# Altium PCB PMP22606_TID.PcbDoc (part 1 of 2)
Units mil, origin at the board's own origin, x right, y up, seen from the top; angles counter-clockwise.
Board outline 6300 x 4500 mil, 2 copper layers (Top Layer, Bottom Layer), stack 62 mil thick; 94 components, 37 nets, 207 pads, 120 vias.
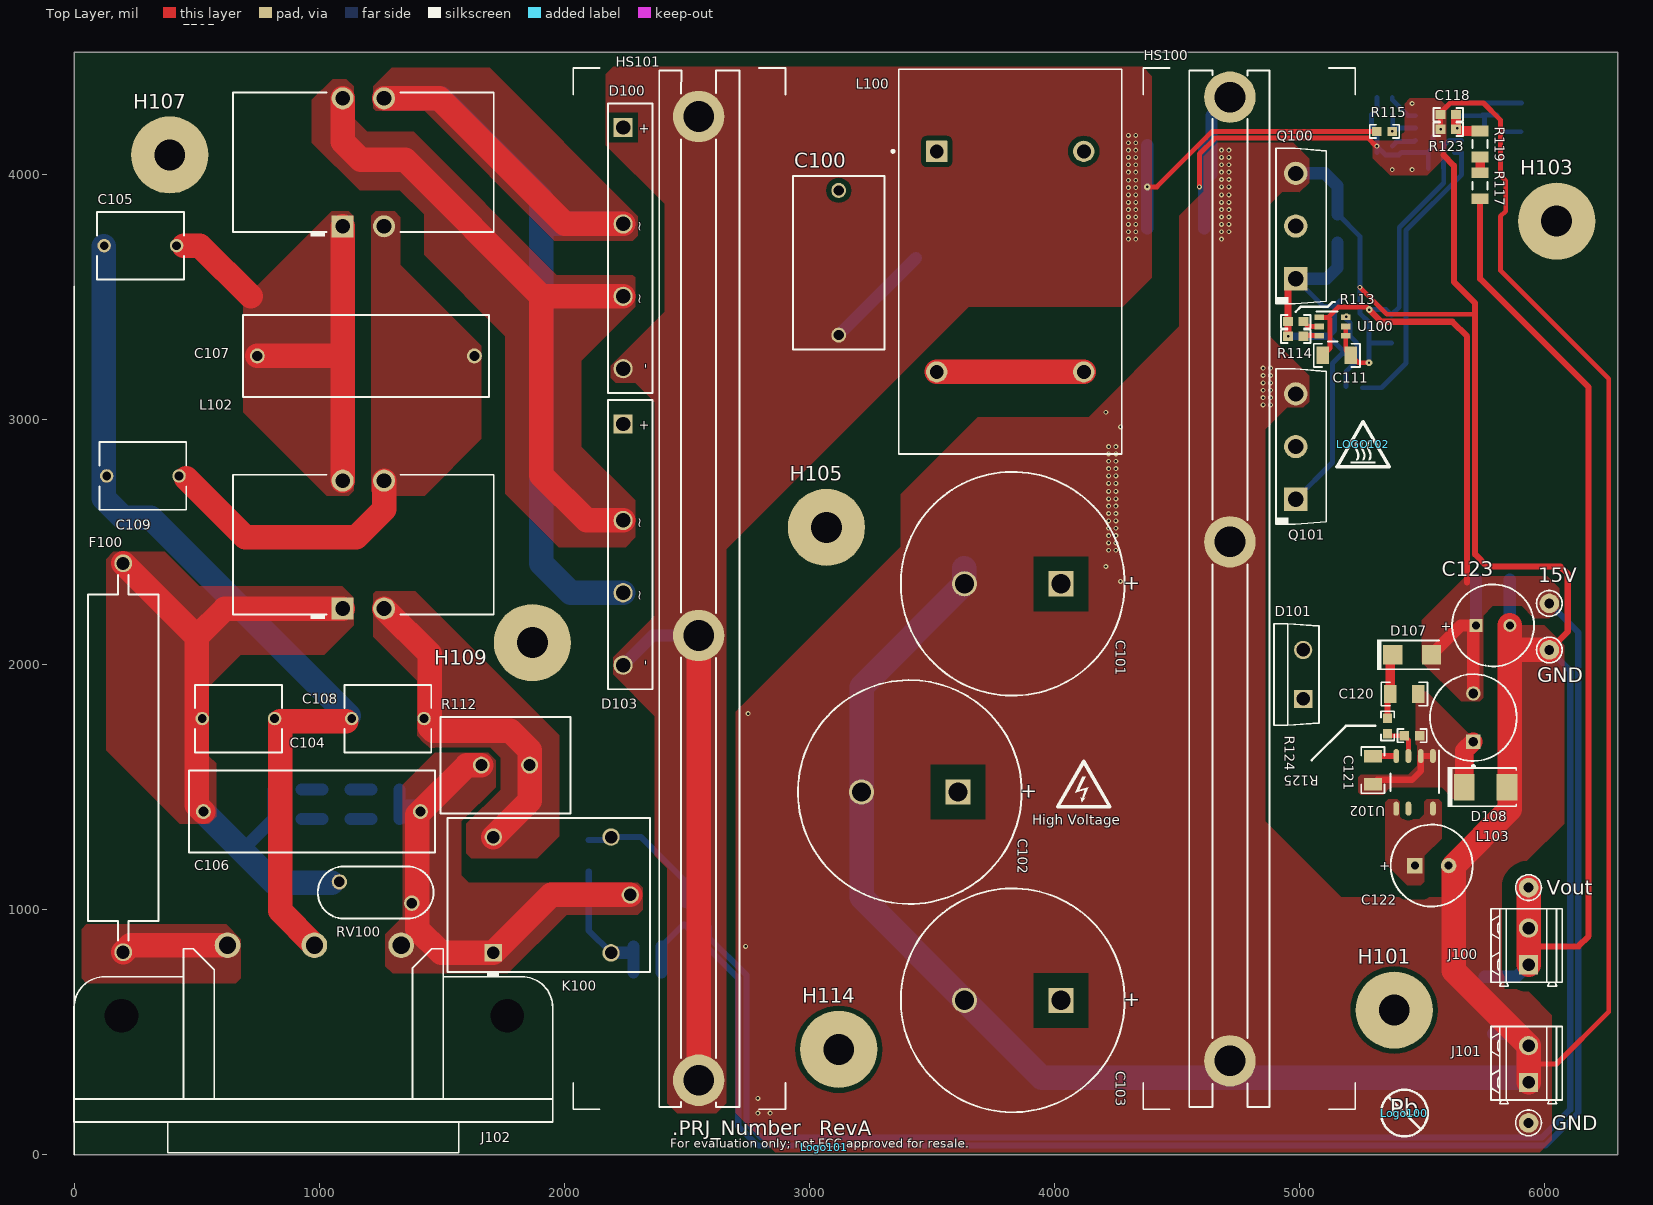
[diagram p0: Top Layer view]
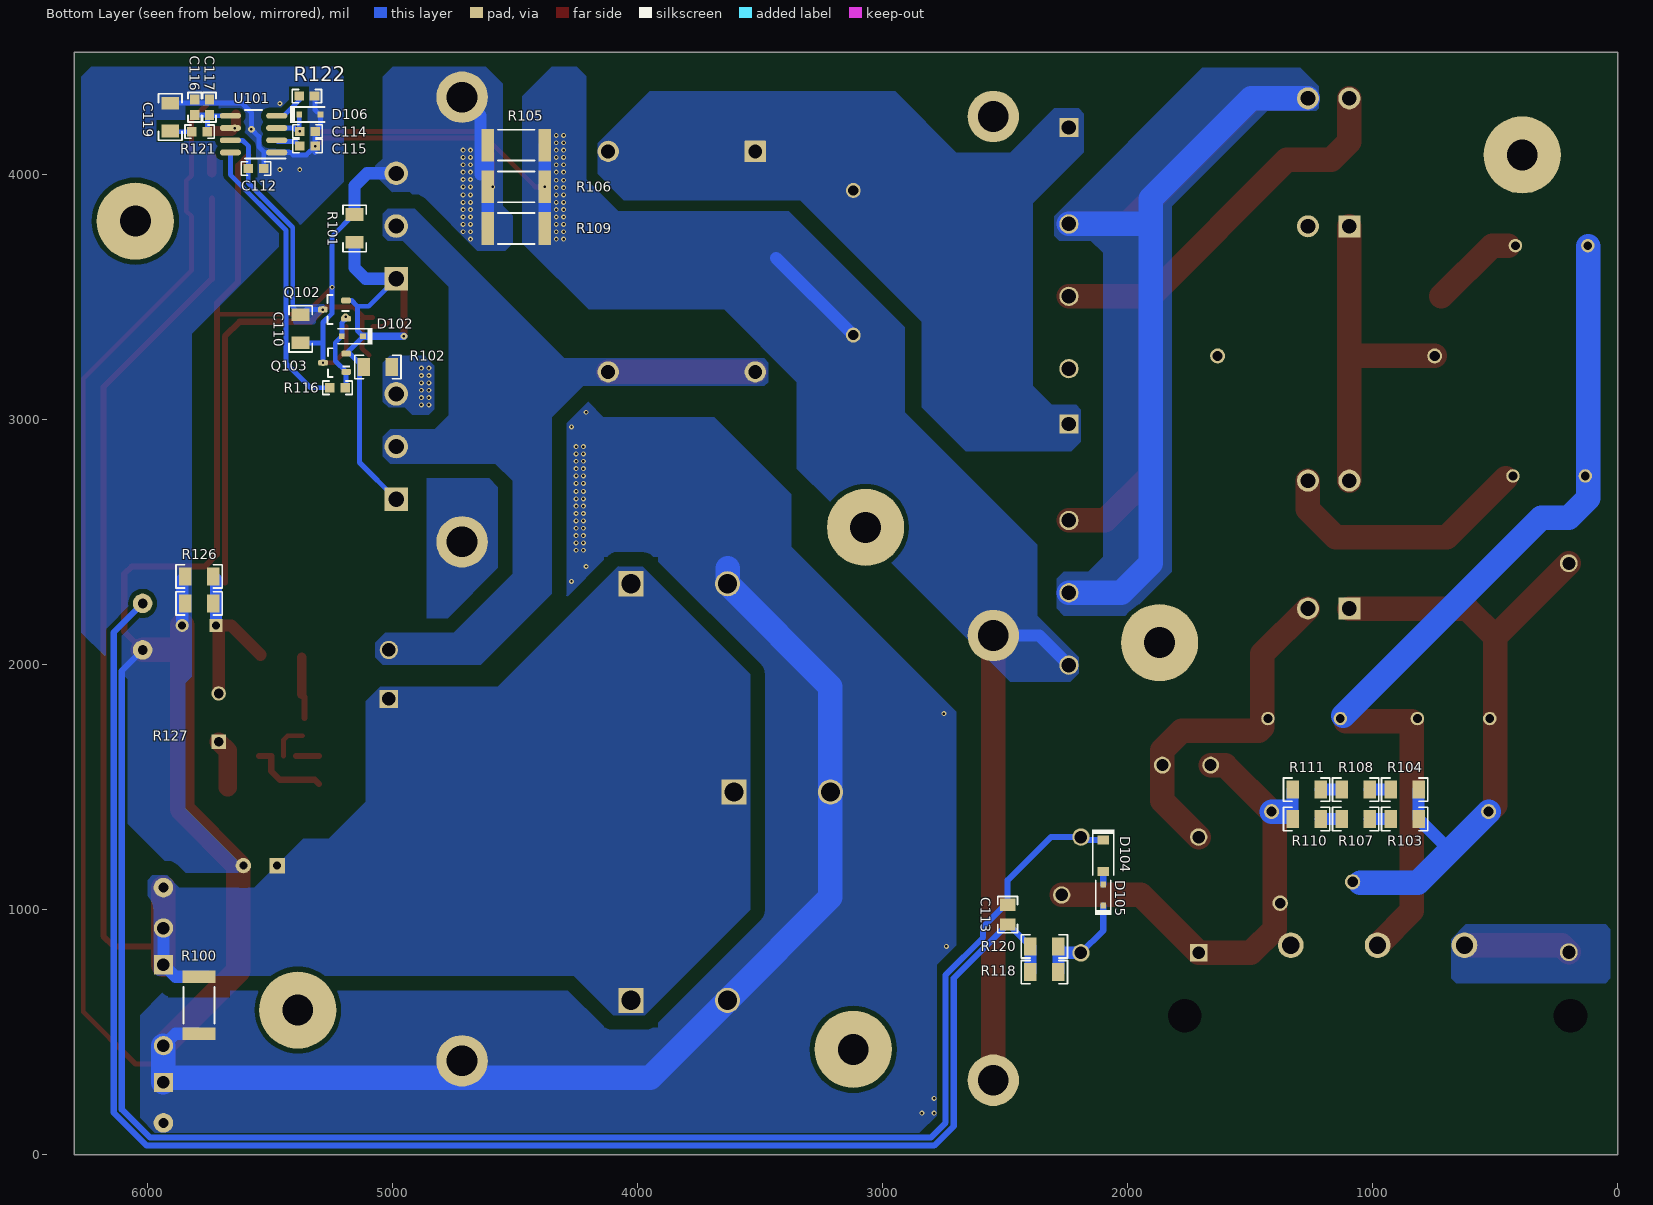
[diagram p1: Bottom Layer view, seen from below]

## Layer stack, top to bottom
Top Solder: solder mask 0.4, Solder Resist, Dk 3.5
Top Layer: signal copper 1.4
Dielectric1: core 59.2, FR-4, Dk 4.8
Bottom Layer: signal copper 1.4
Bottom Solder: solder mask 0.4, Solder Resist, Dk 3.5

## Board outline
0,0 6300,0 6300,4500 0,4500

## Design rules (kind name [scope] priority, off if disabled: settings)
AcuteAngle [All] p1: minimum=4.50000000000000E+0001 checktracksonly=FALSE
AssemblyTestPointUsage [All] p1: valid=2
Clearance Clearance_1 [InNetClass('HV') vs (InNet('GND') OR InNet('NetC103_2'))] p1: gap=60 ignorepadtopadclearanceinfootprint=FALSE except(0: Arc-Hole Track-Hole SMDPad-Hole THPad-Hole Via-Hole Fill-Hole Poly-Hole Region-Hole Text-Hole)
Clearance Clearance_Keepouts [((IsTrack Or IsArc) And Not InPoly) And IsFree and IsKeepOut vs ((IsTrack Or IsArc) And Not InPoly) And IsFree and IsKeepOut] p2: gap=0 ignorepadtopadclearanceinfootprint=FALSE
Clearance Clearance_BoardEdge_MountingHoles [OnCopper and InComponentClass('Mounting Holes') vs IsKeepOut] p3: gap=40 ignorepadtopadclearanceinfootprint=FALSE except(0: Arc-Hole Track-Hole SMDPad-Hole THPad-Hole Via-Hole Fill-Hole Poly-Hole Region-Hole Text-Hole)
Clearance Clearance_BoardEdge_Poly [OnCopper and InPoly vs IsKeepOut] p4: gap=25 ignorepadtopadclearanceinfootprint=FALSE except(0: Arc-Hole Track-Hole SMDPad-Hole THPad-Hole Via-Hole Fill-Hole Poly-Hole Region-Hole Text-Hole)
Clearance Clearance_BoardEdge [OnCopper and Not InComponentClass('Logo') and not InComponentClass('FiducialMark') and not InRegion(1000,500,4000,800) and Not IsKeepout vs IsKeepOut] p5: gap=75 ignorepadtopadclearanceinfootprint=FALSE except(0: Arc-Hole Track-Hole SMDPad-Hole THPad-Hole Via-Hole Fill-Hole Poly-Hole Region-Hole Text-Hole)
Clearance Clearance_Poly [InPolygon] p6: gap=20 ignorepadtopadclearanceinfootprint=FALSE except(0: Arc-Hole Track-Hole SMDPad-Hole THPad-Hole Via-Hole Fill-Hole Poly-Hole Region-Hole Text-Hole)
Clearance [All] p7: gap=7.87 ignorepadtopadclearanceinfootprint=FALSE except(0: Arc-Hole Track-Hole SMDPad-Hole THPad-Hole Via-Hole Fill-Hole Poly-Hole Region-Hole Text-Hole)
ComponentClearance ComponentClearance_MountingHoles_FiducialMarks [InComponentClass('Mounting Holes') vs InComponentClass('FiducialMark')] p1: gap=20 collisioncheckmode=3 verticalgap=10 showdistances=FALSE
ComponentClearance ComponentClearance_Shunt [InComponentClass('Header') vs InComponentClass('Shunt')] p2: gap=0 collisioncheckmode=3 verticalgap=0 showdistances=FALSE
ComponentClearance ComponentClearance_Logo [InComponentClass('Logo')] p3: gap=5 collisioncheckmode=3 verticalgap=10 showdistances=FALSE
ComponentClearance ComponentClearance_ScrewToNut [(HasFootprint('NY PMS 440 0025 PH')) vs (HasFootprint('Keystone_1902C'))] p4: gap=20 collisioncheckmode=3 verticalgap=100000 showdistances=FALSE
ComponentClearance ComponentClearance_MountingHoles [InComponentClass('Mounting Holes')] p5: gap=20 collisioncheckmode=3 verticalgap=10 showdistances=FALSE
ComponentClearance ComponentClearance_SmallPassives [HasFootprint('0201*') or HasFootprint('0402*') or HasFootprint('0508') or HasFootprint('0603*') or HasFootprint('0612') or HasFootprint('0805*') or HasFootprint('0815*') or HasFootprint('0830*') or HasFootprint('1206*') or HasFootprint('1210*') or HasFootprint('1808*') or HasFootprint('1812*') or HasFootprint('1825*') or HasFootprint('2010*') or HasFootprint('2220*') or HasFootprint('2225*') or HasFootprint('2512*') or HasFootprint('2728*') or HasFootprint('3518*') vs HasFootprint('0201*') or HasFootprint('0402*') or HasFootprint('0508') or HasFootprint('0603*') or HasFootprint('0612') or HasFootprint('0805*') or HasFootprint('0815*') or HasFootprint('0830*') or HasFootprint('1206*') or HasFootprint('1210*') or HasFootprint('1808*') or HasFootprint('1812*') or HasFootprint('1825*') or HasFootprint('2010*') or HasFootprint('2220*') or HasFootprint('2225*') or HasFootprint('2512*') or HasFootprint('2728*') or HasFootprint('3518*')] p6: gap=20 collisioncheckmode=3 verticalgap=20 showdistances=FALSE
ComponentClearance ComponentClearance_THtoSMT [IsThruComponent vs IsSMTComponent] p7: gap=10 collisioncheckmode=3 verticalgap=10 showdistances=FALSE
ComponentClearance ComponentClearance_THtoTH [IsThruComponent vs IsThruComponent] p8: gap=10 collisioncheckmode=3 verticalgap=10 showdistances=FALSE
ComponentClearance [All] p9: gap=10 collisioncheckmode=3 verticalgap=10 showdistances=FALSE
DiffPairsRouting [All] p1: maxlimit=100 minlimit=10 mostfreqgap=10 toplayer_minwidth=15 toplayer_maxwidth=15 toplayer_prefwidth=15 bottomlayer_minwidth=15 bottomlayer_maxwidth=15 bottomlayer_prefwidth=15 maxuncoupledlength=1000
FabricationTestPointUsage TestPointUsage [All] p1: valid=2 allowmultiple=FALSE
FabricationTestpoint Testpoint [All] p1: side=3 testpointundercomponent=TRUE minsize=40 maxsize=100 preferedsize=60 minholesize=0 maxholesize=40 preferedholesize=32 testpointgrid=1 allowsidetop=TRUE allowsidebottom=TRUE usegrid=TRUE gridtolerance=0.01
FanoutControl Fanout_LCC [IsLCC] p1: bgadir=Out bgaviamode=Centered fanoutstyle=Auto fanoutdirection=Alternating viagrid=1 // Fanout_LCC (Default Rule)
FanoutControl Fanout_BGA [IsBGA] p2: bgadir=Out bgaviamode=Centered fanoutstyle=Auto fanoutdirection=Alternating viagrid=1 // Fanout_BGA (Default Rule)
FanoutControl Fanout_Default [All] p4: bgadir=Out bgaviamode=Centered fanoutstyle=Auto fanoutdirection=Alternating viagrid=1 // Fanout_Default (Default Rule)
FanoutControl Fanout_Small [(CompPinCount < 5)] p5: bgadir=Out bgaviamode=Centered fanoutstyle=Auto fanoutdirection=OutThenIn viagrid=1 // Fanout_Small (Default Rule)
Height [All] p1: minheight=0 maxheight=3000 prefheight=500
HoleSize [All] p1: absolutevalues=TRUE maxlimit=251 minlimit=7 maxpercent=80.000 minpercent=20.000
MinimumAnnularRing MinimumAnnularRing_ThermalPadVias [IsVia and InAnyComponent] p1: minimumring=5.91
MinimumAnnularRing [All] p2: minimumring=5
MinimumSolderMaskSliver MinimumSolderMaskSliver_Logo [InComponentClass('Logo') vs InComponentClass('Logo')] p1: minsoldermaskwidth=0.7
MinimumSolderMaskSliver [All] p2: minsoldermaskwidth=2
PlaneConnect [All] p1: planeconnectstyle=Relief reliefexpansion=10 reliefentries=4 reliefconductorwidth=10 reliefairgap=10
PolygonConnect PolygonConnect_8 [All vs IsNamedPolygon('C104_1') Or  IsNamedPolygon('GND') Or  IsNamedPolygon('B+') Or  IsNamedPolygon('B+') Or  IsNamedPolygon('C107_2') Or  IsNamedPolygon('D100_2') Or  IsNamedPolygon('15V') Or  IsNamedPolygon('C106_2') Or  IsNamedPolygon('C120_2') Or  IsNamedPolygon('C100_2') Or  IsNamedPolygon('GND') Or  IsNamedPolygon('D101_2') Or  IsNamedPolygon('C105_1') Or  IsNamedPolygon('F100_1') Or  IsNamedPolygon('D100_3') Or  IsNamedPolygon('C108_2') Or  IsNamedPolygon('C100_1') Or  IsNamedPolygon('F100_1') Or  IsNamedPolygon('D100_2') Or  IsNamedPolygon('C100_2')] p1: connectstyle=Direct reliefconductorwidth=10 reliefentries=4 polygonreliefangle="90 Angle" airgapwidth=10
PolygonConnect PolygonConnect_7 [All vs IsNamedPolygon('F100_1') Or  IsNamedPolygon('C103_1') Or  IsNamedPolygon('C106_1') Or  IsNamedPolygon('D100_2') Or  IsNamedPolygon('C106_1') Or  IsNamedPolygon('C105_1') Or  IsNamedPolygon('C109_2') Or  IsNamedPolygon('B+') Or  IsNamedPolygon('C107_2') Or  IsNamedPolygon('C108_2') Or  IsNamedPolygon('F100_1') Or  IsNamedPolygon('C103_2') Or  IsNamedPolygon('C107_2') Or  IsNamedPolygon('D100_3') Or  IsNamedPolygon('D101_2')] p2: connectstyle=Direct reliefconductorwidth=10 reliefentries=4 polygonreliefangle="90 Angle" airgapwidth=10
PolygonConnect PolygonConnect_6 [All vs IsNamedPolygon('GND2') Or  IsNamedPolygon('SGND') Or  IsNamedPolygon('GND1') Or  IsNamedPolygon('C901_1') Or  IsNamedPolygon('SGND') Or  IsNamedPolygon('GND2') Or  IsNamedPolygon('GND1')] p3: connectstyle=Direct reliefconductorwidth=10 reliefentries=4 polygonreliefangle="90 Angle" airgapwidth=10
PolygonConnect PolygonConnect_5 [All vs IsNamedPolygon('GND1') Or  IsNamedPolygon('GND1')] p4: connectstyle=Direct reliefconductorwidth=10 reliefentries=4 polygonreliefangle="90 Angle" airgapwidth=10
PolygonConnect PolygonConnect_4 [All vs IsNamedPolygon('C21_1') Or  IsNamedPolygon('C5_1') Or  IsNamedPolygon('C12_2') Or  IsNamedPolygon('C2_2') Or  IsNamedPolygon('C13_1') Or  IsNamedPolygon('C28_1') Or  IsNamedPolygon('C6_1') Or  IsNamedPolygon('GND') Or  IsNamedPolygon('GND2') Or  IsNamedPolygon('C14_1') Or  IsNamedPolygon('C13_1') Or  IsNamedPolygon('Q1_3') Or  IsNamedPolygon('C14_1') Or  IsNamedPolygon('C5_1') Or  IsNamedPolygon('GND2') Or  IsNamedPolygon('C28_1') Or  IsNamedPolygon('D5_2') Or  IsNamedPolygon('D6_2') Or  IsNamedPolygon('D2_1') Or  IsNamedPolygon('C12_2') Or  IsNamedPolygon('D2_1') Or  IsNamedPolygon('C4_1') Or  IsNamedPolygon('C4_1') Or  IsNamedPolygon('C2_2') Or  IsNamedPolygon('GND') Or  IsNamedPolygon('C33_1') Or  IsNamedPolygon('C9_1')] p5: connectstyle=Direct reliefconductorwidth=10 reliefentries=4 polygonreliefangle="90 Angle" airgapwidth=10
PolygonConnect PolygonConnect_3 [All vs IsNamedPolygon('C28_1') Or  IsNamedPolygon('C12_2') Or  IsNamedPolygon('C28_1') Or  IsNamedPolygon('C9_1') Or  IsNamedPolygon('D5_2') Or  IsNamedPolygon('C12_2') Or  IsNamedPolygon('C2_2') Or  IsNamedPolygon('C14_1') Or  IsNamedPolygon('C4_1') Or  IsNamedPolygon('C14_1') Or  IsNamedPolygon('D6_2') Or  IsNamedPolygon('GND2') Or  IsNamedPolygon('Q1_3') Or  IsNamedPolygon('C5_1') Or  IsNamedPolygon('D2_1') Or  IsNamedPolygon('C4_1') Or  IsNamedPolygon('C13_1') Or  IsNamedPolygon('C5_1') Or  IsNamedPolygon('C13_1') Or  IsNamedPolygon('C33_1') Or  IsNamedPolygon('D2_1') Or  IsNamedPolygon('GND') Or  IsNamedPolygon('GND') Or  IsNamedPolygon('GND2') Or  IsNamedPolygon('C2_2') Or  IsNamedPolygon('C6_1') Or  IsNamedPolygon('C21_1')] p6: connectstyle=Direct reliefconductorwidth=10 reliefentries=4 polygonreliefangle="90 Angle" airgapwidth=10
PolygonConnect PolygonConnect_2 [All vs IsNamedPolygon('C21_1') Or  IsNamedPolygon('C4_1') Or  IsNamedPolygon('D5_2') Or  IsNamedPolygon('C5_1') Or  IsNamedPolygon('C14_1') Or  IsNamedPolygon('C13_1') Or  IsNamedPolygon('C4_1') Or  IsNamedPolygon('C33_1') Or  IsNamedPolygon('C12_2') Or  IsNamedPolygon('D2_1') Or  IsNamedPolygon('C2_2') Or  IsNamedPolygon('C28_1') Or  IsNamedPolygon('C12_2') Or  IsNamedPolygon('D2_1') Or  IsNamedPolygon('C5_1') Or  IsNamedPolygon('Q1_3') Or  IsNamedPolygon('GND') Or  IsNamedPolygon('D6_2') Or  IsNamedPolygon('C6_1') Or  IsNamedPolygon('C2_2') Or  IsNamedPolygon('C14_1') Or  IsNamedPolygon('C28_1') Or  IsNamedPolygon('C13_1') Or  IsNamedPolygon('C9_1') Or  IsNamedPolygon('GND')] p7: connectstyle=Direct reliefconductorwidth=10 reliefentries=4 polygonreliefangle="90 Angle" airgapwidth=10
PolygonConnect PolygonConnect_1 [All vs IsNamedPolygon('C28_1') Or  IsNamedPolygon('D5_2') Or  IsNamedPolygon('C5_1') Or  IsNamedPolygon('C5_1') Or  IsNamedPolygon('D2_1') Or  IsNamedPolygon('C21_1') Or  IsNamedPolygon('C9_1') Or  IsNamedPolygon('C4_1') Or  IsNamedPolygon('C14_1') Or  IsNamedPolygon('C28_1') Or  IsNamedPolygon('C6_1') Or  IsNamedPolygon('C12_2') Or  IsNamedPolygon('C33_1') Or  IsNamedPolygon('C4_1') Or  IsNamedPolygon('C13_1') Or  IsNamedPolygon('C12_2') Or  IsNamedPolygon('D6_2') Or  IsNamedPolygon('C2_2') Or  IsNamedPolygon('C14_1') Or  IsNamedPolygon('D2_1') Or  IsNamedPolygon('C2_2') Or  IsNamedPolygon('C13_1')] p8: connectstyle=Direct reliefconductorwidth=10 reliefentries=4 polygonreliefangle="90 Angle" airgapwidth=10
PolygonConnect [All] p9: connectstyle=Relief reliefconductorwidth=10 reliefentries=4 polygonreliefangle="90 Angle" airgapwidth=10
RoutingVias ThermalPadVias [IsVia and InAnyComponent] p1: holewidth=7.87 width=19.68 viastyle="Through Hole" minholewidth=7.87 minwidth=19.68 maxholewidth=12.99 maxwidth=23.62
RoutingVias [All] p2: holewidth=10 width=34 viastyle="Through Hole" minholewidth=7.87 minwidth=20 maxholewidth=40 maxwidth=65
SilkToBoardRegionClearance [Not ((IsComment or IsDesignator) And (Hide <> 'False')) and not InRegion(1000,500,4000,800)] p1:
SilkToSilkClearance SilkToSilkClearance_Pb-FreeLogo [(HasFootprint('Pb-Free_Overlay_Medium') OR HasFootprint('Pb-Free_Overlay_Small')) vs (HasFootprint('Pb-Free_Overlay_Medium') OR HasFootprint('Pb-Free_Overlay_Small'))] p1: silktosilkclearance=0
SilkToSilkClearance [All] p2: silktosilkclearance=1
SilkToSolderMaskClearance "Silk to Solder Mask Opening" [All] p1: minsilkscreentomaskgap=1 clearancetoexposedcopper=FALSE
SolderMaskExpansion [All] p1: expansion=1.97
Width [All] p1: maxlimit=100 minlimit=6 preferedwidth=10 checkconnectedcopper=TRUE
14 further rules are at their usual default settings.

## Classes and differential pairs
net class HV: B+ NetC100_1 NetC104_1 NetC105_1 NetC106_2 NetC108_2 NetD101_2 NetF100_1
component class "Mounting Holes": H101 H103 H105 H107 H109 H114

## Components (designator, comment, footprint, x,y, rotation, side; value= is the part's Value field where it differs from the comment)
15V "5000" Keystone5000 6020,2250 r0 top
C100 "450MPK105J" MPK_1800x950 3120,3640 r270 top value=1uF
C101 "450HXG180MEFCSN22X45" SMQ_2200X2500 3830,2330 r180 top value=180uF
C102 "450HXG180MEFCSN22X45" SMQ_2200X2500 3410,1480 r180 top value=180uF
C103 "450HXG180MEFCSN22X45" SMQ_2200X2500 3830,630 r180 top value=180uF
C104 "DE6E3KJ222MN3A" E_900x700x900 670,1780 r0 top value=2200pF
C105 "DE6E3KJ222MN3A" E_900x700x900 270,3710 r180 top value=2200pF
C106 "ECQ-U2A474ML" CAPRR2250W80L2550T850H1750 970,1400 r0 top value=0.47uF
C107 "ECQ-U2A474ML" CAPRR2250W80L2550T850H1750 1190,3260 r0 top value=0.47uF
C108 "DE6E3KJ222MN3A" E_900x700x900 1280,1780 r0 top value=2200pF
C109 "DE6E3KJ222MN3A" E_900x700x900 280,2770 r0 top value=2200pF
C110 "C3216X7R1H105K160AB" 1206 5375.2,3370 r270 bottom value=1uF
C111 "C3216X7R1H105K160AB" 1206 5152.88,3262.49 r0 top value=1uF
C112 "C0603C474K8RACTU" 0603 5557.52,4024.88 r180 bottom value=0.47uF
C113 "0805YD105KAT2A" 0805_HV 2490,980 r270 bottom value=1uF
C114 "06031C471JAT2A" 0603 5347.52,4176.34 r180 bottom value=470pF
C115 "C0603C102J5RACTU" 0603 5347.52,4116.34 r180 bottom value=1000pF
C116 "C0603C105K4PACTU" 0603 5807.52,4274.88 r90 bottom value=1uF
C117 "C0603C474K8RACTU" 0603 5747.52,4274.88 r90 bottom value=0.47uF
C118 "CL10C102JB8NNNC" 0603 5607.52,4244.88 r180 top value=1000pF
C119 "GRM31MR61A106KE19L" 1206 5907.52,4234.88 r90 bottom value=10uF
C120 "12065C104JAT2A" 1206 5428.5,1880 r0 top value=0.1uF
C121 "12065C223KAT2A" 1206 5300,1569.56 r270 top value=0.022uF
C122 "ECA-2WHG010" NHG_800x1150 5540,1180 r0 top value=1uF
C123 "EKMG250ELL221MHB5D" Chemi-Con_800x1150 5790,2160 r0 top value=220uF
D100 "DFB2560" 5S 2240,3700 r270 top value=600V
D101 "CVFD20065A" TO-220-2 5015.2,1960 r90 top value=650V
D102 "BAT54HT1G" sod-323 5163.9,3340.16 r0 bottom value=30V
D103 "DFB2560" 5S 2240,2490 r270 top value=600V
D104 "MMSZ4699T1G" SOD-123 2100,1220 r270 bottom value=12V
D105 "BAS316,115" sod-323 2100,1060 r90 bottom value=100V
D106 "MMDL914-TP" SOD-323 5337.52,4244.88 r180 bottom value=100V
D107 "ES1J-TP" SMA 5460,2040 r0 top value=600V
D108 "MURS160-13-F" SMB 5760,1500.05 r0 top value=600V
F100 "0325020.MXP" FUSE_0325 200,1620 r90 top
GND "5001" Keystone5001 5935.2,130 r90 top
GND "5001" Keystone5001 6020,2060 r90 top
H101 "NY PMS 440 0025 PH" "NY PMS 440 0025 PH" 5386.93,590.32 r0 top
H103 "NY PMS 440 0025 PH" "NY PMS 440 0025 PH" 6050,3810 r0 top
H105 "NY PMS 440 0025 PH" "NY PMS 440 0025 PH" 3070,2560 r0 top
H107 "NY PMS 440 0025 PH" "NY PMS 440 0025 PH" 390,4080 r0 top
H109 "NY PMS 440 0025 PH" "NY PMS 440 0025 PH" 1870,2090 r0 top
H114 "NY PMS 440 0025 PH" "NY PMS 440 0025 PH" 3120,430 r0 top
"High Voltage" "DANGER HIGH VOLTAGE" IEC_HighVoltage_Small 4120,1507.56 r0 top (schematic designator "High Voltage100")
HS100 "782653B04250G" HEATSINK_782653B04250G 4795.2,2310 r270 top
HS101 "782653B04250G" HEATSINK_782653B04250G 2470,2310 r90 top
J100 "691214310002" Wurth_691214310002 5935.2,850 r90 top
J101 "691214310002" Wurth_691214310002 5935.2,370 r90 top
J102 "703W-00/54" CONN_QUALTEK-703W-0054 980,460 r180 top
K100 "G5LE-1-E-36-DC12" RELAY_875 1990,1060 r90 top
L100 "RLTI-1328" FP-RLTI-1328_PTH_INDUCTOR-MFG 3820,3644.77 r0 top
L101 "750318527" 7840-21-0021 1180,4050 r90 top value=1.68mH
L102 "750318527" 7840-21-0021 1180,2490 r90 top value=1.68mH
L103 "744741222" WE-TI_8055 5710,1784 r90 top value=2.2mH
Logo100 "Pb-Free Symbol" Pb-Free_Overlay_Medium 5428.5,170 r0 top
Logo101 "FCC disclaimer" FCC_disclaimer 3060,30 r0 top
LOGO102 "CAUTION HOT SURFACE" IEC_HotSurface_Small 5260,2900 r0 top
Q100 "IPW65R095C7" TO-247 4985.2,3790 r90 top value=650V
Q101 "IPW65R095C7" TO-247 4985.2,2890 r90 top value=650V
Q102 "FMMT620TA" SOT-23 5237.32,3449.06 r0 bottom value=80V
Q103 "FMMT718TA" SOT-23 5236.85,3232.17 r0 bottom value="20 V"
R100 "CRCW2512330KJNEG" 2512 5790,610 r90 bottom value=330k
R101 "CRCW120620K0JNEA" 1206 5155.2,3780 r270 bottom value=20k
R102 "CRCW120620K0JNEA" 1206 5060,3214.85 r0 bottom value=20k
R103 "CRCW1206432KFKEA" 1206 870,1370 r180 bottom value=432k
R104 "CRCW1206432KFKEA" 1206 870,1490 r180 bottom value=432k
R105 "1-2176057-4" 2512 4495.2,4120 r0 bottom value=0.036
R106 "1-2176057-4" 2512 4495.2,3950 r0 bottom value=0.036
R107 "CRCW1206432KFKEA" 1206 1070,1370 r180 bottom value=432k
R108 "CRCW1206432KFKEA" 1206 1070,1490 r180 bottom value=432k
R109 "1-2176057-4" 2512 4495.2,3780 r0 bottom value=0.036
R110 "CRCW1206432KFKEA" 1206 1270,1370 r180 bottom value=432k
R111 "CRCW1206432KFKEA" 1206 1270,1490 r180 bottom value=432k
R112 "TWW10J10RE" TWW10 1760,1590 r180 top value=10
R113 "CRCW060310R0JNEAHP" 0603 4985.2,3400 r0 top value=10
R114 "CRCW06030000Z0EA" 0603 4985.2,3340 r180 top value=0
R115 "CRCW0603221RFKEA" 0603 5347.52,4176.34 r180 top value=221
R116 "CRCW060310R0JNEAHP" 0603 5225.2,3130 r0 bottom value=10
R117 "CRCW1206499KFKEA" 1206L 5737.52,3954.88 r270 top value=499k
R118 "CRCW1206150RJNEA" 1206 2340,745.04 r0 bottom value=150
R119 "CRCW1206499KFKEA" 1206L 5737.52,4124.88 r270 top value=499k
R120 "CRCW1206150RJNEA" 1206 2340,850 r0 bottom value=150
R121 "CRCW06035K90FKEA" 0603 5787.52,4174.88 r180 bottom value=5.90k
R122 "CRCW060316K2FKEA" 0603 5350,4320 r0 bottom value=16.2k
R123 "CRCW060313K3FKEA" 0603 5607.52,4184.88 r0 top value=13.3k
R124 "CRCW0603137KFKEA" 0603 5360,1750 r90 top value=137k
R125 "CRCW060310K0FKEA" 0603 5460,1710 r180 top value=10.0k
R126 "CRCW120612K0JNEA" 1206 5789.69,2360 r180 bottom value=12k
R127 "CRCW120612K0JNEA" 1206 5789.69,2250 r180 bottom value=12k
RV100 "S10K275E2" VAR_S10K275E2 1230,1070 r180 top
U100 "UCC27511DBVR" DBV0006A_N 5135.2,3380 r0 top
U101 "UCC28180D" D0008A_N 5567.52,4164.88 r0 bottom
U102 "UCC28880DR" D0007A_N 5470,1519.74 r270 top
Vout "5000" Keystone5000 5935.2,1090 r90 top

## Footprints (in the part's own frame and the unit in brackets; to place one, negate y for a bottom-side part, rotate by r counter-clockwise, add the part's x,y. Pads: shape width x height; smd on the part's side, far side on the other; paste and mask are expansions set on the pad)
5S [mm] "TH, 4-Leads, Body 4.6x30mm"
  rect 2x2 hole 1.5: 1(-12.5,0)
  round 2 hole 1.5: 2(-2.5,0) 3(5,0) 4(12.5,0)
  silkscreen extent -15,-1.55 15,3.05, body extent -15,-1.55 15,3.05, height 24
0603 [mm] "0603 from SM-752 data"
  rect 1x0.95 smd: 1(-0.8,0) 2(0.8,0)
  silkscreen extent -1.52,-0.69 1.52,0.69, body extent -0.87,-0.47 0.87,0.47, height 1
0805_HV [mil] "0805 with 30mil clearance between pads"
  rect 50x63 smd: 1(-40,0) 2(40,0)
  silkscreen extent -74,-40 74,40, body extent -43,-29 43,29, height 43
1206 [mm] "1206 from SM-752 data"
  rect 1.3x1.85 smd: 1(-1.45,0) 2(1.45,0)
  silkscreen extent -2.4,-1.21 2.4,1.21, body extent -1.7,-0.9 1.7,0.9, height 1.35
1206L [mm] "1206 from SM-752 data"
  rect 1.1x1.75 smd: 1(-1.35,0) 2(1.35,0)
  silkscreen extent -0.4,-0.77 0.4,0.77, body extent -1.7,-0.9 1.7,0.9, height 1.35
2512 [mm] "Chip Resistor, Body 6.3x3.2mm, IPC Medium Density"
  rect 1.3x3.4 smd: 1(-2.95,0) 2(2.95,0)
  silkscreen extent -1.9,-1.6 1.9,1.6, body extent -3.22,-1.67 3.22,1.67, height 0.71
7840-21-0021 [mil] "TH, 4-Leads, Dia 1064mil"
  rect 90x90 hole 60: 1(-261,84.5)
  round 90 hole 60: 2(-261,-84.5) 3(261,-84.5) 4(261,84.5)
  silkscreen extent -303,-532 285,532, body extent -281,-532 281,532, height 1064
CAPRR2250W80L2550T850H1750 [mm] "PANASONIC"
  round 1.55 hole 1.05: 1(-11.25,0) 2(11.25,0)
  silkscreen extent -12.75,-4.25 12.75,4.25, body extent -12.75,-4.25 12.75,4.25, height 17.5
Chemi-Con_800x1150 [mm] "TH, 2-Leads, Dia 8mm"
  rect 1.35x1.35 hole 0.85: 1(-1.75,0)
  round 1.35 hole 0.85: 2(1.75,0)
  silkscreen extent -4.25,-4.25 4.25,4.25, body extent -4.22,-4.24 4.24,4.24, height 13.01
CONN_QUALTEK-703W-0054 [mil] "AC Receptacle"
  round 105 hole 70: 1(354.33,-395) 2(-354.33,-395) 3(0,-395)
  round 39.37 hole 137.8 unplated: MH1(-787.4,-107.36) MH2(787.4,-107.36)
  silkscreen extent -972,-380 981,452, body extent -972,-477 981,452, height 1130
D0007A_N [mm] "SOIC, 7-Leads, Body 4.9x3.9mm, Pitch 1.27mm, IPC Medium Density"
  oval 1.45x0.6 smd: 1(-2.725,1.905) 2(-2.725,0.635) 3(-2.725,-0.635) 4(-2.725,-1.905) 5(2.725,-1.905) 6(2.725,-0.635) 8(2.725,1.905)
  silkscreen extent -3.32,-2.5 1.1,2.52, body extent -3.01,-2.45 3.01,2.45, height 1.75
D0008A_N [mm] "SOIC, 8-Leads, Body 4.9x3.9mm, Pitch 1.27mm, IPC Medium Density"
  oval 2.2x0.6 smd: 1(-2.4,1.905) 2(-2.4,0.635) 3(-2.4,-0.635) 4(-2.4,-1.905) 5(2.4,-1.905) 6(2.4,-0.635) 7(2.4,0.635) 8(2.4,1.905)
  silkscreen extent -3.3,-2.5 0.9,2.5, body extent -3,-2.45 3,2.45, height 1.63
DBV0006A_N [mm] "SOT23, 6-Leads, Body 2.9x1.6mm, Pitch 0.95mm, Lead Span 2.8mm, IPC Medium Density"
  rrect17% 1x0.6 smd: 1(-1.375,0.95) 2(-1.375,0) 3(-1.375,-0.95) 4(1.375,-0.95) 5(1.375,0) 6(1.375,0.95)
  silkscreen extent -1.68,-1.55 0.5,1.55, body extent -1.42,-1.46 1.42,1.46, height 1.12
E_900x700x900 [mm] "TH, 2- Leads, Body 9x7mm, Pin Spacing 7.5mm"
  round 1.4 hole 0.9: 1(-3.75,0) 2(3.75,0)
  silkscreen extent -4.5,-3.5 4.5,3.5, body extent -4.49,-3.5 4.49,3.5, height 11.96
FCC_disclaimer [mil]
FP-RLTI-1328_PTH_INDUCTOR-MFG [mm]
  rrect5% 2.2x2.2 hole 1.45 paste-1000 mask+0: 1(-7.62,11.43)
  round 2.2 hole 1.45 paste-1000 mask+0: 2(7.62,11.43) 3(7.62,-11.43) 4(-7.62,-11.43)
  silkscreen extent -12.28,-19.94 11.56,19.94, body extent -11.66,-20.04 11.66,20.04, height 0.25
FUSE_0325 [mm] "TH, 2-Leads, Dia 6.985mm, Pin Spacing 40.32mm"
  round 1.85 hole 1.35: 1(-20.16,0) 2(20.16,0)
  silkscreen extent -18.95,-3.64 18.95,3.64, body extent -20.7,-3.64 20.7,3.64, height 7.26
HEATSINK_782653B04250G [mil] "Aavid"
  round 210 hole 125: 1(-2006.1,-78.66) 2(-191.14,-78.66) 3(1926.97,-78.66)
  silkscreen extent -2125,-433 2125,433, body extent -2125,-430 2120,420, height 1122
IEC_HighVoltage_Small [mil]
  silkscreen extent -107,-88 107,97
IEC_HotSurface_Small [mil]
  silkscreen extent -107,-93 107,92
Keystone5000 [mil] "For Keystone 500x miniature loop terminals"
  round 80 hole 40: 1(0,0)
  silkscreen extent -52,-52 52,52, body extent -49,-49 49,49, height 182
Keystone5001 [mil] "For Keystone 500x miniature loop terminals"
  round 80 hole 40: 1(0,0)
  silkscreen extent -52,-52 52,52, body extent -49,-49 49,49, height 182
MPK_1800x950 [mm] "TH, 2-Leads, Body 18x9.5mm, Lead Spacing 15mm"
  round 1.55 hole 1.05: 1(-7.5,0) 2(7.5,0)
  silkscreen extent -9,-4.75 9,4.75, body extent -9,-4.75 9,4.75, height 14
NHG_800x1150 [mm] "Panasonic"
  rect 1.6x1.6 hole 0.838: 1(-1.75,0)
  round 1.6 hole 0.838: 2(1.75,0)
  silkscreen extent -4.25,-4.25 4.25,4.25, body extent -4.25,-4.25 4.26,4.25, height 12.51
"NY PMS 440 0025 PH" [mm] "4-40 nylon screw and mounting hole"
  round 8 hole 3.2: 1(0,0)
  body extent -3.3,-3.3 3.3,3.3, height 2.69
Pb-Free_Overlay_Medium [mil]
  silkscreen extent -95,-95 95,95
RELAY_875 [mm] "TH, 5-Leads, Body 21x16mm"
  rect 1.8x1.8 hole 1.3: 1(-6,7.1)
  round 1.8 hole 1.3: 2(6,7.1) 3(0,-7.1) 4(-6,-5.1) 5(6,-5.1)
  silkscreen extent -8.5,-9.15 8,11.85, body extent -8,-9.15 8,11.85, height 20.6
SMA [mm] "Molded Diode, 2-Leads, Body 4.3x2.6mm, IPC Medium Density, based on OnSemi component dimensions and land pattern"
  rect 2x2 smd: 1(-2,0) 2(2,0)
  silkscreen extent -3.66,-1.57 2.79,1.57, body extent -2.6,-1.3 2.6,1.3, height 2.42
SMB [mil] "Molded Diode, 2-Leads, Body 5.4x3.6mm, IPC Medium Density, based on OnSemi component dimensions"
  rect 85x107.99 smd: 1(-87.01,0) 2(87.01,0)
  silkscreen extent -155,-82 125,82, body extent -106,-71 106,71, height 91
SMQ_2200X2500 [mm] "United Chemi-Con Inc"
  rect 2.6x2.6 hole 2: 1(-5,0)
  round 2.6 hole 2: 2(5,0)
  silkscreen extent -11.6,-11.6 11.6,11.6, body extent -11.41,-11.48 11.47,11.48, height 27.01
SOD-123 [mm] "On Semi recommended land pattern"
  rect 0.915x1.22 smd: 1(-1.637,0) 2(1.637,0)
  silkscreen extent -2.74,-1.17 2.03,1.17, body extent -1.93,-0.9 1.93,0.9, height 1.35
sod-323 [mm] "NXP recommended land pattern"
  rect 0.6x0.6 smd paste-0.05: 1(-1.1,0) 2(1.1,0)
  silkscreen extent -2.06,-0.86 1.53,0.86, body extent -1.3,-0.67 1.3,0.68, height 1.1
SOD-323 [mm] "NXP recommended land pattern"
  rect 0.6x0.6 smd paste-0.05: 1(-1.1,0) 2(1.1,0)
  silkscreen extent -2.06,-0.86 1.53,0.86, body extent -1.3,-0.67 1.3,0.68, height 1.1
SOT-23 [mm] "SOT23, 3-Leads, Body 2.9x1.3mm, Pitch 0.95mm, Lead Span 2.5mm, IPC Medium Density"
  rrect50% 1x0.6 smd: 1(-1.2,0.95) 2(-1.2,-0.95) 3(1.2,0)
  silkscreen extent -1.58,-1.5 0.7,1.5, body extent -1.16,-1.45 1.21,1.45, height 1
TO-220-2 [mm] "CREE"
  rect 1.9x1.9 hole 1.4: 1(-2.54,0)
  round 1.9 hole 1.4: 2(2.54,0)
  silkscreen extent -5.25,-1.64 5.26,3.01, body extent -5.21,-1.57 5.21,3.12, height 19.47
TO-247 [mil] "Standard TO-247"
  rect 95x95 hole 62: 1(-215,0)
  round 95 / inner round 74.8 / far side round 96 hole 62: 2(0,0) 3(215,0)
  silkscreen extent -318,-124 318,81, body extent -318,-124 318,81, height 1007
TWW10 [mm] "TH, 2-Leads, Body 13.5x10mm, Pin Spacing 5mm"
  round 1.75 hole 1.25: 1(-2.5,0) 2(2.5,0)
  silkscreen extent -6.75,-5 6.75,5, body extent -6.7,-5 6.81,5, height 50
VAR_S10K275E2 [mm] "EPCOS"
  round 1.6 hole 1.1: 1(-3.75,1.1) 2(3.75,-1.1)
  silkscreen extent -6,-2.7 6,2.7, body extent -5.98,-2.7 5.98,2.7, height 14.99
WE-TI_8055 [mm] "Wurth"
  rect 1.5x1.5 hole 1: 1(-2.5,0)
  round 1.5 hole 1: 2(2.5,0)
  silkscreen extent -5.21,-4.5 4.5,4.5, body extent -5.89,-5.88 5.81,5.83, height 5.51
Wurth_691214310002 [mm] "WE"
  rect 2x2 hole 1.3: 1(-1.905,0)
  round 2 hole 1.3: 2(1.905,0)
  silkscreen extent -4.12,-3.5 3.9,3.9, body extent -4.12,-3.5 3.9,3.9, height 8.52

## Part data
15V Vout: "Test Point, Miniature, Red, TH", Color=Red, Manufacturer=Keystone, Supplier Part Number 1=36-5000-ND
C100: "CAP, Film, 1 £gF, 450 V,+/- 5%, TH", Cap_Case=18x9.5mm, Manufacturer=Rubycon, Supplier Part Number 1=1189-1822-ND, Tolerance_%=5, Value2=450V, ValueDisplayed=1£gF
C101 C102 C103: library part ESMQ451VSN101MP25S, "CAP ALUM 180UF 450V 20% SNAP", Cap_Case=22x25, Manufacturer=Rubycon, Supplier Part Number 1=1189-1973-ND, Tolerance_%=20, Value1=Unknown, Value2=450V, ValueDisplayed=180£gF
C104 C105 C108 C109: "CAP, CERM, 2200 pF, 300 V, +/- 20%, E, TH, 2- Leads, Body 9x7mm, Pin Spacing 7.5mm", Cap_Case=9x7x9mm, Manufacturer=MuRata, Supplier Part Number 1=DE6E3KJ222MN3A-ND, TempCo=E, Tolerance_%=20, Value1=Unknown, Value2=300V, ValueDisplayed=2200pF
C106 C107: "CAP, Film, 0.47 £gF, 275 V, +/- 20%, TH", Cap_Case="Radial 25x8.5x18.5", Manufacturer=Panasonic, Supplier Part Number 1=P10734-ND, Tolerance_%=20, Value1=Unknown, Value2=275V, ValueDisplayed=0.47£gF
C110 C111: "CAP, CERM, 1 £gF, 50 V, +/- 10%, X7R, 1206", Cap_Case=1206, Manufacturer=TDK, Supplier Part Number 1=445-1423-1-ND, TempCo=X7R, Tolerance_%=10, Value1=Unknown, Value2=50V, ValueDisplayed=1£gF
C112 C117: "CAP, CERM, 0.47 £gF, 10 V, +/- 10%, X7R, 0603", Cap_Case=0603, Manufacturer=Kemet, Supplier Part Number 1=399-4923-1-ND, TempCo=X7R, Tolerance_%=10, Value1=Unknown, Value2=10V, ValueDisplayed=0.47£gF
C113: "CAP, CERM, 1uF, 16V, +/-10%, X5R, 0805", Cap_Case=0805, Manufacturer=AVX, Supplier Part Number 1=478-1411-1-ND, TempCo=X5R, Tolerance_%=10, Value1="0.012 ohm", Value2=16V, ValueDisplayed=1£gF
C114: "CAP, CERM, 470 pF, 100 V, +/- 5%, X7R, 0603", Cap_Case=0603, Manufacturer=AVX, Supplier Part Number 1=478-3709-1-ND, TempCo=X7R, Tolerance_%=5, Value1="0.397 ohm", Value2=100V, ValueDisplayed=470pF
C115: "CAP, CERM, 1000 pF, 50 V, +/- 5%, X7R, 0603", Cap_Case=0603, Manufacturer=Kemet, Supplier Part Number 1=399-1083-1-ND, TempCo=X7R, Tolerance_%=5, Value1=Unknown, Value2=50V, ValueDisplayed=1000pF
C116: "CAP, CERM, 1 £gF, 16 V, +/- 10%, X5R, 0603", Cap_Case=0603, Manufacturer=Kemet, Supplier Part Number 1=399-5090-1-ND, TempCo=X5R, Tolerance_%=10, Value1=Unknown, Value2=16V, ValueDisplayed=1£gF
C118: "CAP, CERM, 1000 pF, 50 V, +/- 5%, X7R, 0603", Cap_Case=0603, Manufacturer="Samsung Electro-Mechanics", Supplier Part Number 1=1276-1091-1-ND, TempCo=X7R, Tolerance_%=5, Value1=Unknown, Value2=50V, ValueDisplayed=1000pF
C119: "CAP, CERM, 10 £gF, 10 V, +/- 10%, X5R, 1206", Cap_Case=1206, Manufacturer=MuRata, Supplier Part Number 1=GRM31MR61A106KE19-ND, TempCo=X5R, Tolerance_%=10, Value1=Unknown, Value2=10V, ValueDisplayed=10£gF
C120: "CAP, CERM, 0.1uF, 50V, +/-5%, X7R, 1206", Cap_Case=1206, Manufacturer=AVX, Supplier Part Number 1=478-3797-1-ND, TempCo=X7R, Tolerance_%=5, Value1="0.037 ohm", Value2=50V, ValueDisplayed=0.1£gF
C121: "CAP, CERM, 0.022uF, 50V, +/-10%, X7R, 1206", Cap_Case=1206, Manufacturer=AVX, Supplier Part Number 1=478-1546-1-ND, TempCo=X7R, Tolerance_%=10, Value1="0.079 ohm", Value2=50V, ValueDisplayed=0.022µF
C122: "CAP, AL, 1 £gF, 450 V, +/- 20%, TH", Cap_Case=8x11.5mm, Manufacturer=Panasonic, Supplier Part Number 1=P5872-ND, Tolerance_%=20, Value2=450V, ValueDisplayed=1£gF
C123: "CAP, AL, 220 £gF, 25 V, +/- 20%, TH", Cap_Case=8x11.5mm, Manufacturer=Chemi-Con, Supplier Part Number 1=565-1308-ND, Tolerance_%=20, Value2=25V, ValueDisplayed=220£gF
D100 D103: library part D25XB60-7000, "Bridge Rectifiers 600V 25A Glass Pass. Bridge Rectifier", Manufacturer="On Semi", Value1=3.5A, Value2=1.05V
D101: library part C3D08060A, "DIODE SCHKY SIC 650V 20A TO-220", Manufacturer=Cree, Supplier Part Number 1=CVFD20065A-ND, Value1=20A, Value2=1.8V
D102: "Diode, Schottky, 30 V, 0.2 A, SOD-323", Manufacturer="ON Semiconductor", Supplier Part Number 1=BAT54HT1OSCT-ND, Value1=0.2A, Value2=0.35V
D104: "Diode, Zener, 12 V, 500 mW, SOD-123", Manufacturer="ON Semiconductor", Power_W=0.5, Supplier Part Number 1=MMSZ4699T1GOSCT-ND, Value1=0.5W
D105: "Diode, Ultrafast, 100 V, 0.25 A, SOD-323", Manufacturer="NXP Semiconductor", Supplier Part Number 1=568-5003-1-ND, Value1=0.25A, Value2=1.4V
D106: library part CMP-0029045-2, "Diode, Switching, 100 V, 0.2 A, SOD-323", Manufacturer="Micro Commercial Components", Value1=0.2A, Value2=1V
D107: library part ES1D-13-F, "DIODE FAST REC 600V 1A DO214AC", Manufacturer="Diodes Inc.", Supplier Part Number 1=ES1J-TPCT-ND, Value1=1A
D108: "Diode, Ultrafast, 600V, 1A, SMB", Manufacturer="Diodes Inc.", Supplier Part Number 1=MURS160-FDICT-ND, Value1=1A, Value2=1.25V
F100: "Fuse, 20 A, 60 V, TH", Irating_A=20A, Manufacturer=Littelfuse, Supplier Part Number 1=F3336-ND
GND GND: "Test Point, Miniature, Black, TH", Color=Black, Manufacturer=Keystone, Supplier Part Number 1=36-5001-ND
H101 H103 H105 H107 H109 H114: "Machine Screw, Round, #4-40 x 1/4, Nylon, Philips panhead", DigiKeyPartNumber=H542-ND, Manufacturer="B&F Fastener Supply"
"High Voltage": library part IEC_HighVoltage, "IEC 61010-1 High Voltage Warning"
HS100 HS101: "HEATSINK VERT MAX CLIP, BLACK, 4.25 INCHES", Manufacturer=Aavid, Supplier Part Number 1=782653B04250G-ND
J100 J101: "Terminal Block, 2x1, 3.81mm, 24-16 AWG, 10A, 300VAC, TH", Manufacturer="Wurth Elektronik eiSos"
J102: "AC Receptacle, 10A 250VAC", Manufacturer="Qualtek Electronics Corporation", Supplier Part Number 1=Q220-ND
K100: library part 875B-1CC-F-S-12VDC, "Relay, SPDT ( 1 Form C), 16A, 12 VDC, TH", Coil Current="30 mA", Coil Power="360 mW", Coil Resistance="400 ohms", Coil Voltage="12 VDC", Contact Rating=16A, Manufacturer=Omron, Turn Off Voltage (Min)="0.6 VDC", Turn On Voltage (Max)="9 VDC"
L100: library part CMP-0088184-1, "INDUCTOR WITH KOOL MU MAX CORE", Manufacturer="Renco Electronics"
L101 L102: library part 7840-21-0021, "Coupled inductor, 1.68 mH,  A,  ohm, TH", Manufacturer=Wurth, ValueDisplayed=1.68mH
L103: library part 744741101, "FIXED IND 2.2MH 210MA 11 OHM TH", Manufacturer="Wurth Elektronik", ValueDisplayed=2.2mH
Logo100: library part CMP-0074839-1
Logo101: library part CMP-0074847-1, "FCC_disclaimer"
LOGO102: library part IEC_HotSurface, "IEC 61010-1 Hot Surface Warning"
Q100 Q101: library part IPW60R045CP, "MOSFET N-CH 650V 24A TO247", Alternate Manufacturer=None, Manufacturer="Infineon Technologies", Supplier Part Number 1=IPW65R095C7XKSA1-ND, Value1="? ohm"
Q102: library part "FMMT497, Zetex", "TRANS NPN 80V 1.5A SOT23-3", Manufacturer=Diodes, Supplier Part Number 1=FMMT620CT-ND, Value1="0.5 A"
Q103: library part "FMMT718TA, Diodes Inc.", "Transistor, PNP, 20 V, 1.5 A, SOT-23", Manufacturer="Diodes Inc.", Supplier Part Number 1=FMMT718CT-ND, Value1="1.5 A", Value2=6
R100: "RES, 330 k, 5%, 1 W, 2512", Manufacturer=Vishay-Dale, Power_W=1, Supplier Part Number 1=541-330KXCT-ND, TempCo="200 ppm/C", Tolerance_%=5, Value1=5%, Value2=1W, Value_Code=330k
R101 R102: "RES, 20 k, 5%, 0.25 W, 1206", Manufacturer=Vishay-Dale, Power_W=0.25, Supplier Part Number 1=541-20KECT-ND, TempCo="200 ppm/C", Tolerance_%=5, Value1=5%, Value2=0.25W, Value_Code=20k0, ValueDisplayed=20k
R103 R104 R107 R108 R110 R111: "RES, 432 k, 1%, 0.25 W, 1206", Manufacturer=Vishay-Dale, Power_W=0.25, Supplier Part Number 1=541-432KFCT-ND, TempCo="100 ppm/C", Tolerance_%=1, Value1=1%, Value2=0.25W, Value_Code=432k
R105 R106 R109: library part WSL2512R0320FEA18, "RES SMD 0.036 OHM 1% 2W 2512", Manufacturer="TE Connectivity", Power_W=2, Supplier Part Number 1=A109683CT-ND, TempCo="75 ppm/C", Tolerance_%=1, Value1=1%, Value2=2W, Value_Code=R036, ValueDisplayed=0.036
R112: "RES, 10, 5%, 10 W, TH", Manufacturer=Ohmite, Power_W=10, TempCo="400 ppm/C", Tolerance_%=5, Value1=5%, Value2=10W, Value_Code=10R0
R113 R116: "RES, 10, 5%, 0.25 W, 0603", Manufacturer=Vishay-Dale, Power_W=0.25, Supplier Part Number 1=541-10SACT-ND, TempCo="200 ppm/C", Tolerance_%=5, Value1=5%, Value2=0.25W, Value_Code=10R0, ValueDisplayed=10
R114: "RES, 0, 5%, 0.1 W, 0603", Manufacturer=Vishay-Dale, Power_W=0.1, Supplier Part Number 1=541-0.0GCT-ND, TempCo="200 ppm/C", Tolerance_%=5, Value1=5%, Value2=0.1W, Value_Code=0000, ValueDisplayed=0
R115: "RES, 221, 1%, 0.1 W, 0603", Manufacturer=Vishay-Dale, Power_W=0.1, Supplier Part Number 1=541-221HCT-ND, TempCo="100 ppm/C", Tolerance_%=1, Value1=1%, Value2=0.1W, Value_Code=221R, ValueDisplayed=221
R117 R119: "RES, 499k ohm, 1%, 0.25W, 1206", Manufacturer=Vishay-Dale, Power_W=0.25, Supplier Part Number 1=541-499KFCT-ND, TempCo="100 ppm/C", Tolerance_%=1, Value1=1%, Value2=0.25W, Value_Code=499k
R118 R120: "RES, 150, 5%, 0.25 W, 1206", Manufacturer=Vishay-Dale, Power_W=0.25, Supplier Part Number 1=541-150ECT-ND, TempCo="200 ppm/C", Tolerance_%=5, Value1=5%, Value2=0.25W, Value_Code=150R, ValueDisplayed=150
R121: "RES, 5.90 k, 1%, 0.1 W, 0603", Manufacturer=Vishay-Dale, Power_W=0.1, Supplier Part Number 1=541-5.90KHCT-ND, TempCo="100 ppm/C", Tolerance_%=1, Value1=1%, Value2=0.1W, Value_Code=5k90, ValueDisplayed=5.90k
R122: "RES, 16.2 k, 1%, 0.1 W, 0603", Manufacturer=Vishay-Dale, Power_W=0.1, Supplier Part Number 1=541-16.2KHCT-ND, TempCo="100 ppm/C", Tolerance_%=1, Value1=1%, Value2=0.1W, Value_Code=16k2, ValueDisplayed=16.2k
R123: "RES, 13.3 k, 1%, 0.1 W, 0603", Manufacturer=Vishay-Dale, Power_W=0.1, Supplier Part Number 1=541-13.3KHCT-ND, TempCo="100 ppm/C", Tolerance_%=1, Value1=1%, Value2=0.1W, Value_Code=13k3, ValueDisplayed=13.3k
R124: "RES, 137 k, 1%, 0.1 W, 0603", Manufacturer=Vishay-Dale, Power_W=0.1, Supplier Part Number 1=541-137KHCT-ND, TempCo="100 ppm/C", Tolerance_%=1, Value1=1%, Value2=0.1W, Value_Code=137k
R125: "RES, 10.0k ohm, 1%, 0.1W, 0603", Manufacturer=Vishay-Dale, Power_W=0.1, Supplier Part Number 1=541-10.0KHCT-ND, TempCo="100 ppm/C", Tolerance_%=1, Value1=1%, Value2=0.1W, Value_Code=10k0
R126 R127: "RES, 12k ohm, 5%, 0.25W, 1206", Manufacturer=Vishay-Dale, Power_W=0.25, Supplier Part Number 1=541-12KECT-ND, TempCo="200 ppm/C", Tolerance_%=5, Value1=5%, Value2=0.25W, Value_Code=12k0
RV100: "Varistor 275V RMS 10MM Radial, TH", Manufacturer="EPCOS Inc", Supplier Part Number 1=495-1433-ND
U100: "Single-Channel High-Speed Low-Side Gate Driver (with 4-A Peak Source and 8-A Peak Sink), DBV0006A", Alternate Manufacturer="Texas Instruments", Alternate PartNumber=UCC27511DBVT
U101: "8-PIN CONTINUOUS CONDUCTION MODE (CCM) PFC CONTROLLER, D0008A", Alternate Manufacturer="Texas Instruments"
U102: library part CMP-0067240-2, "High Voltage Switcher for Non-isolated AC/DC Conversion, D0007A (SOIC-7)", Alternate Manufacturer="Texas Instruments", Alternate PartNumber=UCC28880D

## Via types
v1: diameter 20, hole 10, Top Layer to Bottom Layer, 112 vias
v2: diameter 28, hole 10, Top Layer to Bottom Layer, 8 vias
